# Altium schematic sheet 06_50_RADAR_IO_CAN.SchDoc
size 289 x 396 mm
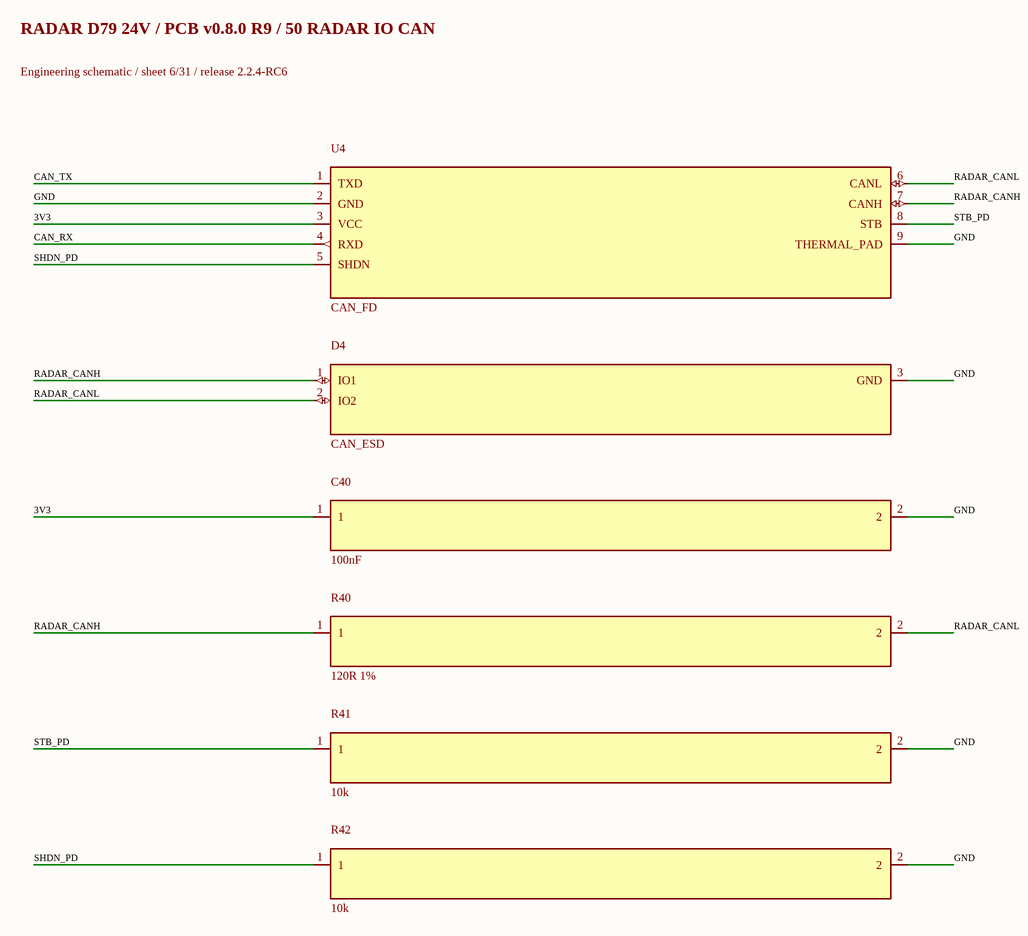
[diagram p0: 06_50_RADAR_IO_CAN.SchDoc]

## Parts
C40  100nF  [C_0402_1005Metric]
D4  CAN_ESD  [SOT-23]
R40  120R 1%  [R_0603_1608Metric]
R41  10k  [R_0603_1608Metric]
R42  10k  [R_0603_1608Metric]
U4  CAN_FD  [Texas_DRB0008A]

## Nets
3V3: C40.1 U4.3(VCC)
CAN_RX: U4.4(RXD)
CAN_TX: U4.1(TXD)
GND: C40.2 D4.3(GND) R41.2 R42.2 U4.2(GND) U4.9(THERMAL_PAD)
RADAR_CANH: D4.1(IO1) R40.1 U4.7(CANH)
RADAR_CANL: D4.2(IO2) R40.2 U4.6(CANL)
SHDN_PD: R42.1 U4.5(SHDN)
STB_PD: R41.1 U4.8(STB)

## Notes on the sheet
- RADAR D79 24V / PCB v0.8.0 R9 / 50 RADAR IO CAN
- Engineering schematic / sheet 6/31 / release 2.2.4-RC6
